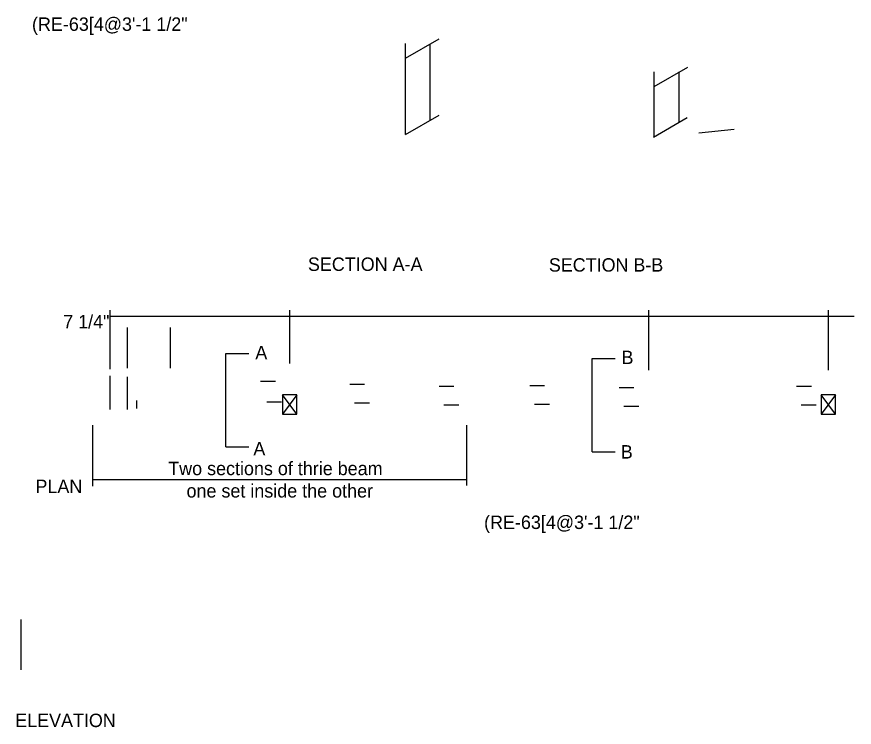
# Model space of a CAD drawing. Extents: x 146 to 619, y 56 to 2134.
# Drawn here: x 146.47 to 175.62, y 55.97 to 80.72 of the extents above; entities that cross this region are included whole.
import ezdxf

# ---------------------------------------------------------------- set-up
doc = ezdxf.new("R2010")
doc.units = 0
doc.layers.add('Level 31', color=7, linetype='Continuous')
doc.layers.add('Level 60', color=7, linetype='Continuous')

msp = doc.modelspace()

# ---------------------------------------------------------------- linework, layer by layer
at = {"layer": 'Level 31'}
for p, q in [((170.208, 76.682), (171.435, 76.805)), ((153.745, 65.737), (153.745, 68.987)), ((153.745, 68.987), (154.545, 68.987)), ((166.495, 65.571), (166.495, 68.821)), ((166.495, 68.821), (167.295, 68.821)), ((156.219, 67.546), (155.719, 66.879)), ((156.219, 66.879), (155.719, 67.546)), ((174.971, 67.547), (174.471, 66.88)), ((174.971, 66.88), (174.471, 67.547)), ((162.125, 66.498), (162.125, 64.398)), ((153.745, 65.737), (154.545, 65.737)), ((166.495, 65.571), (167.295, 65.571))]:
    msp.add_line(p, q, dxfattribs=at)
for points in [[(155.969, 66.879), (156.042, 66.879), (156.219, 66.879), (156.219, 67.546), (155.719, 67.546), (155.719, 66.879), (155.969, 66.879)], [(174.721, 66.88), (174.794, 66.88), (174.971, 66.88), (174.971, 67.547), (174.471, 67.547), (174.471, 66.88), (174.721, 66.88)]]:
    msp.add_lwpolyline(points, dxfattribs=at)
at = {"layer": 'Level 60'}
for p, q in [((160.001, 79.277), (161.17, 79.952)), ((160.001, 76.617), (160.001, 79.786)), ((160.855, 77.107), (160.855, 79.782)), ((168.652, 76.534), (168.652, 78.805)), ((168.661, 78.289), (169.83, 78.964)), ((169.526, 77.046), (169.526, 78.796)), ((160.001, 76.617), (161.17, 77.292)), ((168.637, 76.53), (169.807, 77.205)), ((149.719, 68.44), (149.719, 70.496)), ((149.719, 70.296), (159.094, 70.296)), ((155.969, 68.639), (155.969, 70.496)), ((159.094, 70.296), (168.469, 70.296)), ((168.469, 68.407), (168.469, 70.496)), ((168.472, 70.297), (174.722, 70.297)), ((174.719, 68.407), (174.719, 70.496)), ((174.722, 70.297), (175.621, 70.297)), ((150.324, 68.48), (150.324, 69.9)), ((151.824, 68.48), (151.824, 69.9)), ((149.719, 67.041), (149.719, 68.212)), ((150.324, 67.041), (150.324, 68.181)), ((154.952, 68.023), (155.468, 68.023)), ((158.06, 67.923), (158.576, 67.923)), ((161.168, 67.856), (161.685, 67.856)), ((164.326, 67.873), (164.843, 67.873)), ((167.434, 67.806), (167.951, 67.806)), ((173.611, 67.853), (174.127, 67.853)), ((150.646, 67.078), (150.646, 67.353)), ((155.169, 67.305), (155.686, 67.305)), ((158.227, 67.271), (158.744, 67.271)), ((161.335, 67.205), (161.852, 67.205)), ((164.493, 67.221), (165.01, 67.221)), ((167.601, 67.155), (168.118, 67.155)), ((173.778, 67.201), (174.294, 67.201)), ((149.113, 64.37), (149.113, 66.492)), ((149.143, 64.598), (162.125, 64.598)), ((146.619, 57.976), (146.619, 59.725))]:
    msp.add_line(p, q, dxfattribs=at)

# ---------------------------------------------------------------- texts
at = {"layer": 'Level 31'}
for s, height, p in [('SECTION A-A', 0.467, (156.602, 71.868)), ('SECTION B-B', 0.466, (164.99, 71.843)), ('A', 0.467, (154.771, 68.79)), ('B', 0.466, (167.52, 68.624)), ('A', 0.467, (154.703, 65.443)), ('B', 0.467, (167.493, 65.333)), ('Two sections of thrie beam', 0.467, (151.739, 64.754)), ('PLAN', 0.467, (147.117, 64.131)), ('one set inside the other', 0.467, (152.376, 63.975)), ('ELEVATION', 0.466, (146.415, 55.981))]:
    msp.add_text(s, height=height, dxfattribs=at).set_placement(p)
at = {"layer": 'Level 60'}
for s, height, p in [('(RE-63[4@3\'-1 1/2"', 0.467, (146.997, 80.228)), ('7 1/4"', 0.466, (148.085, 69.866)), ('(RE-63[4@3\'-1 1/2"', 0.467, (162.734, 62.879))]:
    msp.add_text(s, height=height, dxfattribs=at).set_placement(p)

doc.saveas('drawing.dxf')
